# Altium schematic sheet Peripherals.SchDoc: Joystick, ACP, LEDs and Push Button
size A4; Date: 25-FEB-2015; Author: A.B; CompanyName: STMicroelectronics; Address1: 12, Rue Jules HOROWITZ; Address2: 38019 Grenoble; Address3: FRANCE; DocumentNumber: MB1191; Revision: B-02; SheetNumber: 5; SheetTotal: 14; Project: STM32F746G-DISCO
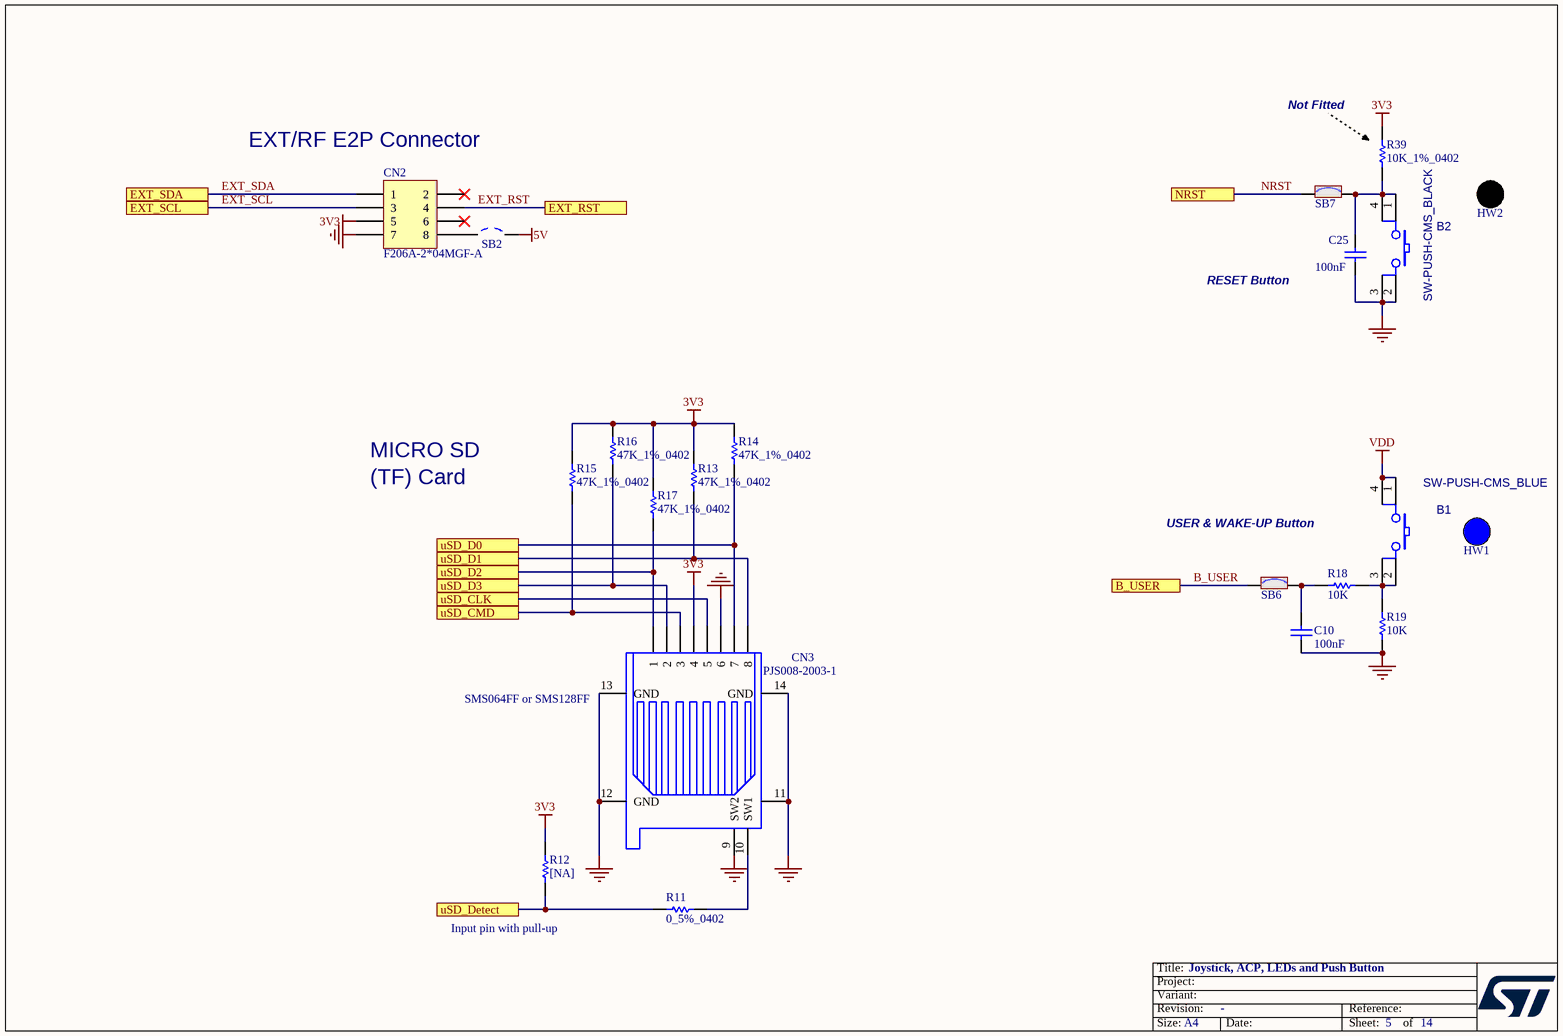
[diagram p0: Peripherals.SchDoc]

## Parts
B1  SW-PUSH-CMS_BLUE  [BP1CMS]
B2  SW-PUSH-CMS_BLACK  [BP1CMS]
C10  100nF  [0402C]
C25  100nF  [0402C]
CN2  F206A-2*04MGF-A  [SSM-104-L-DH]
CN3  PJS008-2003-1  [PJS008-2003-1]
HW1  BUTTON_HAT_BLUE  (value not drawn)  (mechanical)
HW2  BUTTON_HAT_BLACK  (value not drawn)  (mechanical)
R11  0_5%_0402  [0402R]
R12  [NA]  [0402R]
R13  47K_1%_0402  [0402R]
R14  47K_1%_0402  [0402R]
R15  47K_1%_0402  [0402R]
R16  47K_1%_0402  [0402R]
R17  47K_1%_0402  [0402R]
R18  10K  [0402R]
R19  10K  [0402R]
R39  10K_1%_0402  [0402R]
SB2  Solder Bridge OFF  [JP2_SMD]  (value not drawn)
SB6  Solder Bridge ON  [JP2_SMD]  (value not drawn)
SB7  Solder Bridge ON  [JP2_SMD]  (value not drawn)

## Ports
B_USER, EXT_RST, EXT_SCL, EXT_SDA, NRST, uSD_CLK, uSD_CMD, uSD_D0, uSD_D1, uSD_D2, uSD_D3, uSD_Detect

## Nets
3V3: CN2.5 CN3.4 R12.2 R13.2 R14.2 R15.2 R16.2 R17.2 R39.2
5V: SB2.2
GND: B2.2 B2.3 C10.1 C25.1 CN2.7 CN3.6 CN3.9(SW2) CN3.11(GND) CN3.12(GND) CN3.13(GND) CN3.14(GND) R19.1
VDD: B1.1 B1.4
B_USER: SB6.1 ; port B_USER
EXT_RST: CN2.4 ; port EXT_RST
EXT_SCL: CN2.3 ; port EXT_SCL
EXT_SDA: CN2.1 ; port EXT_SDA
NRST: SB7.1 ; port NRST
uSD_CLK: CN3.5 ; port uSD_CLK
uSD_CMD: CN3.3 R15.1 ; port uSD_CMD
uSD_D0: CN3.7 R14.1 ; port uSD_D0
uSD_D1: CN3.8 R13.1 ; port uSD_D1
uSD_D2: CN3.1 R17.1 ; port uSD_D2
uSD_D3: CN3.2 R16.1 ; port uSD_D3
uSD_Detect: R11.1 R12.1 ; port uSD_Detect
NetB1_2: B1.2 B1.3 R18.2 R19.2
NetB2_1: B2.1 B2.4 C25.2 R39.1 SB7.2
NetC10_2: C10.2 R18.1 SB6.2
NetCN2_8: CN2.8 SB2.1
NetCN3_10: CN3.10(SW1) R11.2

Not connected (* = marked no-connect by the designer): CN2 2* 6*

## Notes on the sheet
- (near R39) Not Fitted
- (near CN2) EXT/RF E2P Connector
- RESET Button
- MICRO SD
- (TF) Card
- USER & WAKE-UP Button
- (near CN3) SMS064FF or SMS128FF
- (near R12) Input pin with pull-up

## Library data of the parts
B1 = SW-PUSH-CMS_BLUE: Non-Open Push-Button 0.1A 24V; Manuf_2: FARNELL; Manuf_Part_2: 535-930; Manuf_1: wealthmetal; Manuf_Part_1: TD0341X-G01-BLU; Ref St: 9180120
B2 = SW-PUSH-CMS_BLACK: Non-Open Push-Button 0.1A 24V; Manuf_2: FARNELL; Manuf_Part_2: 535-930; Manuf_1: wealthmetal; Manuf_Part_1: TD0341X-G01-BLA; Ref St: 9180120
C10 C25 = Cap_100nF_X7R_10%_0402: Capacitor,100nF,16V,X7R,10%,0402,YAGEO; Manuf_Part_1: CC0402KRX7R7BB104
CN2 = F206A-2*04MGF-A: Header, 5-Pins, Horizontal Dual row, female SMD; Manuf_2: SAMTEC; Manuf_1: TOWNES
CN3 = microSD-PJS008-2003: Memory Card Connectors MicroSD Card Conn Revrs Mnt Push-Push; Manuf_1: YAMAICHI
HW1 = BUTTON_HAT_BLUE: Round cap, Blue, 6x6mm
HW2 = BUTTON_HAT_BLACK: Black round cap for TSS6x series
R11 = Res_0_5%_0402: Resistor,0,0402,5%,YAGEO; Manuf_Part_1: RC0402JR-070RL; Value: 0; Order: 2363467
R12 = Res_NA_0402: Resistor,[NA],0402; Fitted: NO
R13-R17 = Res_47K_1%_0402: Resistor,47K,0402,1%,YAGEO; Manuf_Part_1: RC0402FR-0747KL; Order: 9239430
R18 R19 = Res_10K_1%_0402: Resistor,10K,0402,1%,YAGEO; Manuf_Part_1: RC0402FR-0710KL
R39 = Res_10K_1%_0402: Resistor,10K,0402,1%,YAGEO; Manuf_Part_1: RC0402FR-0710KL; Fitted: NO
SB2 = SB_OFF: Solder: NO
SB6 SB7 = SB_ON: Solder: YES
